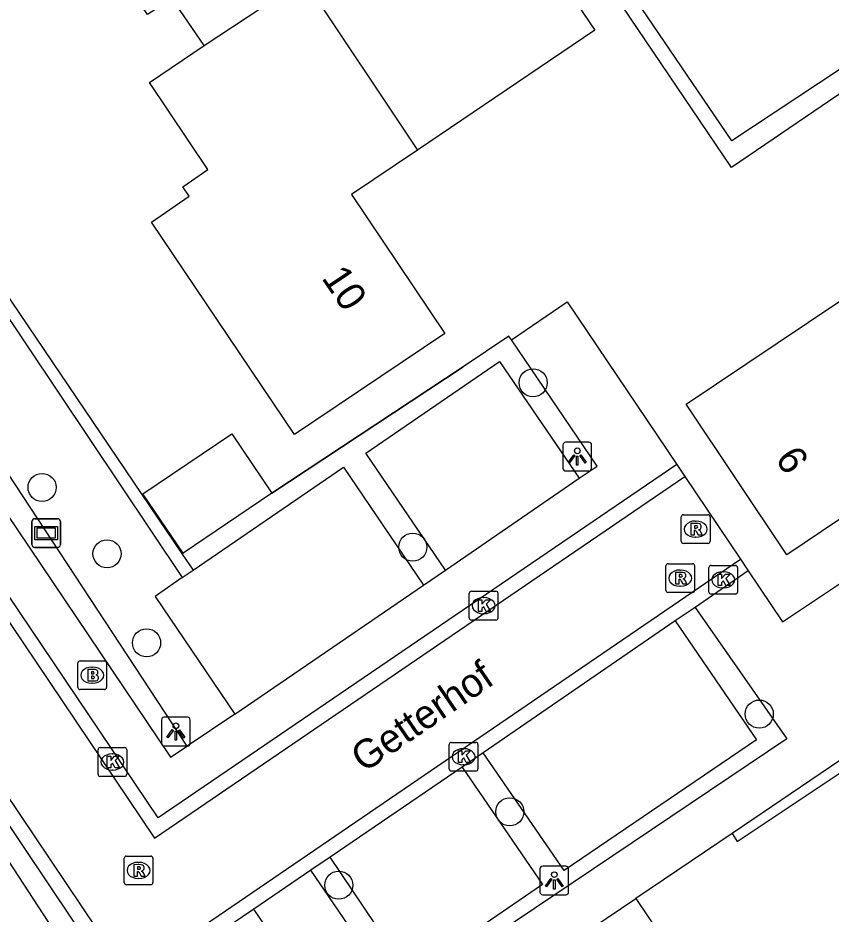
# Model space of a CAD drawing. Extents: x 158797 to 159887, y 384318 to 385255.
# Drawn here: x 158945.21 to 158973.51, y 384624.29 to 384655.5 of the extents above; entities that cross this region are included whole.
import ezdxf

# ---------------------------------------------------------------- set-up
doc = ezdxf.new("R2010")
doc.units = 0
for name, color, linetype in [('IMGEO_Boom', 7, 'Continuous'), ('IMGEO_Brandkraan', 7, 'Continuous'), ('IMGEO_Haag', 7, 'Continuous'), ('IMGEO_Hek', 7, 'Continuous'), ('IMGEO_Kolk', 7, 'Continuous'), ('IMGEO_Lichtpunt', 7, 'Continuous'), ('IMGEO_Openbare_ruimte_label', 7, 'Continuous'), ('IMGEO_Pand', 7, 'Continuous'), ('IMGEO_Pand_nummerreeks', 7, 'Continuous'), ('IMGEO_Parkeervlak_open', 7, 'Continuous'), ('IMGEO_Rijbaan_lokaal_open', 7, 'Continuous'), ('IMGEO_Rioolput', 7, 'Continuous'), ('IMGEO_Straatnaambord', 7, 'Continuous'), ('IMGEO_Voetpad_open', 7, 'Continuous')]:
    doc.layers.add(name, color=color, linetype=linetype)

msp = doc.modelspace()

# ---------------------------------------------------------------- linework, layer by layer
at = {"layer": 'IMGEO_Boom'}
for centre in [(158963.138, 384642.792), (158946.048, 384639.147), (158958.95, 384637.068), (158948.309, 384636.838), (158949.686, 384633.736), (158971.007, 384631.255), (158962.325, 384627.853), (158956.375, 384625.295)]:
    msp.add_circle(centre, 0.489, dxfattribs=at)
at = {"layer": 'IMGEO_Brandkraan'}
for p, q in [((158947.294, 384632.182), (158947.294, 384633.034)), ((158947.369, 384633.108), (158948.221, 384633.108)), ((158947.782, 384632.888), (158947.807, 384632.888)), ((158948.295, 384633.034), (158948.295, 384632.182)), ((158947.805, 384632.328), (158947.78, 384632.328)), ((158948.221, 384632.108), (158947.369, 384632.108))]:
    msp.add_line(p, q, dxfattribs=at)
for points in [[(158947.294, 384632.182), (158947.294, 384633.034)], [(158947.369, 384633.108), (158948.221, 384633.108)], [(158948.295, 384633.034), (158948.295, 384632.182)], [(158947.642, 384632.808), (158947.642, 384632.408), (158947.855, 384632.408)], [(158947.873, 384632.808), (158947.642, 384632.808)], [(158947.821, 384632.727), (158947.767, 384632.727), (158947.767, 384632.651)], [(158947.767, 384632.651), (158947.82, 384632.651)], [(158947.829, 384632.575), (158947.767, 384632.575), (158947.767, 384632.494)], [(158947.767, 384632.494), (158947.829, 384632.494)], [(158948.221, 384632.108), (158947.369, 384632.108)]]:
    msp.add_lwpolyline(points, dxfattribs=at)
for centre, radius, start, end in [((158947.371, 384633.032), 0.0765, 91.552, 178.448), ((158947.371, 384633.032), 0.0765, 91.552, 178.448), ((158948.219, 384633.032), 0.0765, 1.552, 88.448), ((158948.219, 384633.032), 0.0765, 1.552, 88.448), ((158947.822, 384632.689), 0.0379, 267.8285, 90.9355), ((158947.83, 384632.534), 0.0404, 269.8759, 90.5077), ((158947.877, 384632.663), 0.145, 59.4692, 91.5367), ((158947.902, 384632.71), 0.0922, 285.5137, 58.1501), ((158947.907, 384632.518), 0.105, 301.3115, 78.989), ((158947.861, 384632.659), 0.251, 268.6676, 293.5347), ((158947.371, 384632.184), 0.0765, 181.552, 268.448), ((158947.371, 384632.184), 0.0765, 181.552, 268.448), ((158948.219, 384632.184), 0.0765, 271.552, 358.448), ((158948.219, 384632.184), 0.0765, 271.552, 358.448)]:
    msp.add_arc(centre, radius, start, end, dxfattribs=at)
for centre, major_axis, ratio, start_param, end_param in [((158947.781, 384632.608), (-0.387, 0.002), 0.722429, 4.712389, 7.853982), ((158947.806, 384632.608), (-0.39, 0.002), 0.717154, 1.570796, 4.712389)]:
    msp.add_ellipse(centre, major_axis=major_axis, ratio=ratio, start_param=start_param, end_param=end_param, dxfattribs=at)
at = {"layer": 'IMGEO_Haag'}
for points in [[(158977.555, 384656.193), (158970.058, 384651.22), (158941.507, 384693.215), (158927, 384683.401), (158930.702, 384677.442), (158928.077, 384675.641), (158928.67, 384674.688)], [(158982.198, 384627.503), (158986.877, 384630.783), (158991.18, 384624.297), (159005.347, 384633.805), (158997.226, 384645.658), (158986.56, 384661.35), (158977.807, 384655.577), (158970.042, 384650.292), (158941.462, 384692.581), (158927.478, 384683.208), (158931.293, 384677.308), (158928.892, 384675.59), (158929.234, 384675.051), (158928.67, 384674.688)], [(158939.017, 384653.792), (158950.928, 384636.006)], [(158939.596, 384653.583), (158950.919, 384636.829)], [(158951.101, 384630.138), (158937.049, 384651.521), (158936.203, 384651.016)], [(158962.382, 384644.283), (158962.287, 384644.421), (158960.703, 384643.352), (158954.049, 384638.948)], [(158950.958, 384636.856), (158950.919, 384636.829)], [(158950.919, 384636.829), (158951.302, 384636.262)], [(158970.06, 384627.101), (158970.236, 384626.815), (158974.037, 384629.343), (158984.059, 384614.468), (158973.538, 384607.365), (158972.963, 384608.263)], [(158942.998, 384628.997), (158948.959, 384619.868)]]:
    msp.add_lwpolyline(points, dxfattribs=at)
at = {"layer": 'IMGEO_Hek'}
msp.add_lwpolyline([(158954.049, 384638.948), (158960.703, 384643.352)], dxfattribs=at)
at = {"layer": 'IMGEO_Kolk'}
for p, q in [((158969.253, 384635.506), (158969.253, 384636.358)), ((158969.328, 384636.432), (158970.18, 384636.432)), ((158970.254, 384636.358), (158970.254, 384635.506)), ((158969.741, 384636.212), (158969.766, 384636.212)), ((158960.914, 384634.604), (158960.914, 384635.456)), ((158960.989, 384635.53), (158961.841, 384635.53)), ((158961.915, 384635.456), (158961.915, 384634.604)), ((158970.18, 384635.432), (158969.328, 384635.432)), ((158969.764, 384635.652), (158969.739, 384635.652)), ((158961.402, 384635.31), (158961.427, 384635.31)), ((158961.425, 384634.75), (158961.4, 384634.75)), ((158961.841, 384634.53), (158960.989, 384634.53)), ((158948.07, 384630.086), (158948.922, 384630.086)), ((158960.217, 384629.344), (158960.217, 384630.196)), ((158960.292, 384630.27), (158961.144, 384630.27)), ((158961.218, 384630.196), (158961.218, 384629.344)), ((158947.995, 384629.16), (158947.995, 384630.012)), ((158948.483, 384629.866), (158948.508, 384629.866)), ((158948.996, 384630.012), (158948.996, 384629.16)), ((158960.705, 384630.05), (158960.73, 384630.05)), ((158960.728, 384629.49), (158960.703, 384629.49)), ((158948.506, 384629.306), (158948.481, 384629.306)), ((158961.144, 384629.27), (158960.292, 384629.27)), ((158948.922, 384629.086), (158948.07, 384629.086))]:
    msp.add_line(p, q, dxfattribs=at)
for points in [[(158969.253, 384635.506), (158969.253, 384636.358)], [(158969.328, 384636.432), (158970.18, 384636.432)], [(158970.254, 384636.358), (158970.254, 384635.506)], [(158969.574, 384636.132), (158969.697, 384636.132), (158969.697, 384635.981), (158969.827, 384636.132), (158969.991, 384636.132), (158969.845, 384635.981), (158969.998, 384635.732), (158969.846, 384635.732), (158969.761, 384635.896), (158969.697, 384635.829), (158969.697, 384635.732), (158969.574, 384635.732), (158969.574, 384636.132)], [(158960.914, 384634.604), (158960.914, 384635.456)], [(158960.989, 384635.53), (158961.841, 384635.53)], [(158961.915, 384635.456), (158961.915, 384634.604)], [(158970.18, 384635.432), (158969.328, 384635.432)], [(158961.235, 384635.23), (158961.358, 384635.23), (158961.358, 384635.079), (158961.488, 384635.23), (158961.652, 384635.23), (158961.506, 384635.079), (158961.659, 384634.83), (158961.507, 384634.83), (158961.422, 384634.994), (158961.358, 384634.927), (158961.358, 384634.83), (158961.235, 384634.83), (158961.235, 384635.23)], [(158961.841, 384634.53), (158960.989, 384634.53)], [(158948.07, 384630.086), (158948.922, 384630.086)], [(158960.217, 384629.344), (158960.217, 384630.196)], [(158960.292, 384630.27), (158961.144, 384630.27)], [(158961.218, 384630.196), (158961.218, 384629.344)], [(158947.995, 384629.16), (158947.995, 384630.012)], [(158948.316, 384629.786), (158948.439, 384629.786), (158948.439, 384629.635), (158948.569, 384629.786), (158948.733, 384629.786), (158948.587, 384629.635), (158948.74, 384629.386), (158948.588, 384629.386), (158948.503, 384629.55), (158948.439, 384629.483), (158948.439, 384629.386), (158948.316, 384629.386), (158948.316, 384629.786)], [(158948.996, 384630.012), (158948.996, 384629.16)], [(158960.538, 384629.97), (158960.661, 384629.97), (158960.661, 384629.819), (158960.791, 384629.97), (158960.955, 384629.97), (158960.809, 384629.819), (158960.962, 384629.57), (158960.81, 384629.57), (158960.725, 384629.734), (158960.661, 384629.667), (158960.661, 384629.57), (158960.538, 384629.57), (158960.538, 384629.97)], [(158961.144, 384629.27), (158960.292, 384629.27)], [(158948.922, 384629.086), (158948.07, 384629.086)]]:
    msp.add_lwpolyline(points, dxfattribs=at)
for centre, start, end in [((158969.33, 384636.356), 91.552, 178.448), ((158969.33, 384636.356), 91.552, 178.448), ((158970.178, 384636.356), 1.552, 88.448), ((158970.178, 384636.356), 1.552, 88.448), ((158960.991, 384635.454), 91.552, 178.448), ((158960.991, 384635.454), 91.552, 178.448), ((158961.839, 384635.454), 1.552, 88.448), ((158961.839, 384635.454), 1.552, 88.448), ((158969.33, 384635.508), 181.552, 268.448), ((158969.33, 384635.508), 181.552, 268.448), ((158970.178, 384635.508), 271.552, 358.448), ((158970.178, 384635.508), 271.552, 358.448), ((158960.991, 384634.606), 181.552, 268.448), ((158960.991, 384634.606), 181.552, 268.448), ((158961.839, 384634.606), 271.552, 358.448), ((158961.839, 384634.606), 271.552, 358.448), ((158948.072, 384630.01), 91.552, 178.448), ((158948.072, 384630.01), 91.552, 178.448), ((158948.92, 384630.01), 1.552, 88.448), ((158948.92, 384630.01), 1.552, 88.448), ((158960.294, 384630.194), 91.552, 178.448), ((158960.294, 384630.194), 91.552, 178.448), ((158961.142, 384630.194), 1.552, 88.448), ((158961.142, 384630.194), 1.552, 88.448), ((158948.072, 384629.162), 181.552, 268.448), ((158948.072, 384629.162), 181.552, 268.448), ((158948.92, 384629.162), 271.552, 358.448), ((158948.92, 384629.162), 271.552, 358.448), ((158960.294, 384629.346), 181.552, 268.448), ((158960.294, 384629.346), 181.552, 268.448), ((158961.142, 384629.346), 271.552, 358.448), ((158961.142, 384629.346), 271.552, 358.448)]:
    msp.add_arc(centre, 0.0765, start, end, dxfattribs=at)
for centre, major_axis, ratio, start_param, end_param in [((158969.74, 384635.932), (-0.387, 0.002), 0.722429, 4.712389, 7.853982), ((158969.765, 384635.932), (-0.39, 0.002), 0.717154, 1.570796, 4.712389), ((158961.401, 384635.03), (-0.387, 0.002), 0.722429, 4.712389, 7.853982), ((158961.426, 384635.03), (-0.39, 0.002), 0.717154, 1.570796, 4.712389), ((158948.482, 384629.586), (-0.387, 0.002), 0.722429, 4.712389, 7.853982), ((158948.507, 384629.586), (-0.39, 0.002), 0.717154, 1.570796, 4.712389), ((158960.704, 384629.77), (-0.387, 0.002), 0.722429, 4.712389, 7.853982), ((158960.729, 384629.77), (-0.39, 0.002), 0.717154, 1.570796, 4.712389)]:
    msp.add_ellipse(centre, major_axis=major_axis, ratio=ratio, start_param=start_param, end_param=end_param, dxfattribs=at)
at = {"layer": 'IMGEO_Lichtpunt'}
for p, q in [((158965.078, 384640.72), (158964.27, 384640.72)), ((158965.078, 384640.72), (158964.27, 384640.72)), ((158964.176, 384640.625), (158964.176, 384639.818)), ((158964.176, 384640.625), (158964.176, 384639.818)), ((158965.172, 384639.818), (158965.172, 384640.625)), ((158965.172, 384639.818), (158965.172, 384640.625)), ((158964.27, 384639.724), (158965.078, 384639.724)), ((158964.27, 384639.724), (158965.078, 384639.724)), ((158950.206, 384631.048), (158950.206, 384630.241)), ((158950.206, 384631.048), (158950.206, 384630.241)), ((158951.108, 384631.143), (158950.3, 384631.143)), ((158951.108, 384631.143), (158950.3, 384631.143)), ((158951.202, 384630.241), (158951.202, 384631.048)), ((158951.202, 384630.241), (158951.202, 384631.048)), ((158950.3, 384630.147), (158951.108, 384630.147)), ((158950.3, 384630.147), (158951.108, 384630.147)), ((158963.376, 384625.865), (158963.376, 384625.058)), ((158963.376, 384625.865), (158963.376, 384625.058)), ((158964.278, 384625.96), (158963.47, 384625.96)), ((158964.278, 384625.96), (158963.47, 384625.96)), ((158964.372, 384625.058), (158964.372, 384625.865)), ((158964.372, 384625.058), (158964.372, 384625.865)), ((158963.47, 384624.964), (158964.278, 384624.964)), ((158963.47, 384624.964), (158964.278, 384624.964))]:
    msp.add_line(p, q, dxfattribs=at)
for points in [[(158964.55, 384640.289), (158964.589, 384640.261), (158964.401, 384639.999), (158964.363, 384640.026), (158964.55, 384640.289)], [(158964.652, 384640.241), (158964.699, 384640.241), (158964.699, 384639.919), (158964.652, 384639.919), (158964.652, 384640.241)], [(158964.762, 384640.261), (158964.8, 384640.288), (158964.987, 384640.026), (158964.948, 384639.998), (158964.762, 384640.261)], [(158950.58, 384630.712), (158950.619, 384630.684), (158950.431, 384630.422), (158950.393, 384630.449), (158950.58, 384630.712)], [(158950.792, 384630.684), (158950.83, 384630.711), (158951.017, 384630.449), (158950.978, 384630.421), (158950.792, 384630.684)], [(158950.682, 384630.664), (158950.729, 384630.664), (158950.729, 384630.342), (158950.682, 384630.342), (158950.682, 384630.664)], [(158963.75, 384625.529), (158963.789, 384625.501), (158963.601, 384625.239), (158963.563, 384625.266), (158963.75, 384625.529)], [(158963.852, 384625.481), (158963.899, 384625.481), (158963.899, 384625.159), (158963.852, 384625.159), (158963.852, 384625.481)], [(158963.962, 384625.501), (158964, 384625.528), (158964.187, 384625.266), (158964.148, 384625.238), (158963.962, 384625.501)]]:
    msp.add_lwpolyline(points, dxfattribs=at)
for centre in [(158964.675, 384640.423), (158950.705, 384630.846), (158963.875, 384625.663)]:
    msp.add_circle(centre, 0.0994, dxfattribs=at)
for centre, start, end in [((158964.27, 384640.625), 90, 180), ((158964.27, 384640.625), 90, 180), ((158965.078, 384640.625), 0, 90), ((158965.078, 384640.625), 0, 90), ((158964.27, 384639.818), 180, 270), ((158964.27, 384639.818), 180, 270), ((158965.078, 384639.818), 270, 0), ((158965.078, 384639.818), 270, 360), ((158950.3, 384631.048), 90, 180), ((158950.3, 384631.048), 90, 180), ((158951.108, 384631.048), 0, 90), ((158951.108, 384631.048), 0, 90), ((158950.3, 384630.241), 180, 270), ((158950.3, 384630.241), 180, 270), ((158951.108, 384630.241), 270, 0), ((158951.108, 384630.241), 270, 360), ((158963.47, 384625.865), 90, 180), ((158963.47, 384625.865), 90, 180), ((158964.278, 384625.865), 0, 90), ((158964.278, 384625.865), 0, 90), ((158963.47, 384625.058), 180, 270), ((158963.47, 384625.058), 180, 270), ((158964.278, 384625.058), 270, 0), ((158964.278, 384625.058), 270, 360)]:
    msp.add_arc(centre, 0.0946, start, end, dxfattribs=at)
at = {"layer": 'IMGEO_Pand'}
for points in [[(158951.688, 384654.533), (158950.579, 384656.17), (158949.72, 384655.614), (158947.442, 384658.977), (158948.29, 384659.551), (158947.666, 384660.472), (158949.703, 384661.834), (158948.108, 384664.221), (158953.136, 384667.637), (158959.371, 384658.409), (158961.876, 384660.105), (158965.286, 384655.074), (158959.111, 384650.898)], [(158951.688, 384654.533), (158955.154, 384656.841), (158959.111, 384650.898)], [(158959.111, 384650.898), (158956.816, 384649.346), (158960.067, 384644.506), (158954.829, 384640.992), (158949.853, 384648.386), (158951.172, 384649.295), (158950.952, 384649.62), (158951.817, 384650.223), (158949.791, 384653.25), (158951.688, 384654.533)], [(158978.456, 384637.583), (158976.795, 384640.054), (158971.967, 384636.804), (158968.458, 384642.042), (158975.882, 384647.025), (158976.77, 384645.705), (158977.111, 384645.927), (158977.701, 384645.062), (158980.723, 384647.095), (158982.012, 384645.186)], [(158950.958, 384636.856), (158949.554, 384638.926), (158952.648, 384641.018), (158954.049, 384638.948)], [(158954.049, 384638.948), (158950.958, 384636.856)], [(158963.155, 384622.43), (158966.711, 384624.833)], [(158966.711, 384624.833), (158968.976, 384621.467), (158972.244, 384623.666), (158976.039, 384618.066), (158979.246, 384620.233), (158981.95, 384616.231), (158976.507, 384612.552), (158975.269, 384614.383), (158970.878, 384611.416)]]:
    msp.add_lwpolyline(points, dxfattribs=at)
at = {"layer": 'IMGEO_Parkeervlak_open'}
for points in [[(158960.089, 384636.266), (158957.311, 384640.347), (158961.963, 384643.532), (158964.741, 384639.472)], [(158951.302, 384636.262), (158956.541, 384639.854), (158959.328, 384635.75)], [(158950.928, 384636.006), (158949.979, 384635.355), (158952.761, 384631.247)], [(158950.928, 384636.006), (158951.302, 384636.262)], [(158968.085, 384634.504), (158970.914, 384630.355), (158964.22, 384625.803), (158961.404, 384629.901)], [(158960.669, 384629.404), (158963.469, 384625.318), (158958.849, 384622.147), (158956.071, 384626.266)]]:
    msp.add_lwpolyline(points, dxfattribs=at)
at = {"layer": 'IMGEO_Rijbaan_lokaal_open'}
for points in [[(158968.134, 384639.947), (158950.085, 384627.638), (158924.353, 384665.905), (158921.285, 384670.455)], [(158920.881, 384670.173), (158923.955, 384665.633), (158949.957, 384626.932), (158968.418, 384639.524)], [(158968.134, 384639.947), (158968.418, 384639.524)], [(158968.418, 384639.524), (158970.35, 384636.65)], [(158918.871, 384617.212), (158941.972, 384632.67), (158949.064, 384622.099), (158970.35, 384636.65)], [(158970.35, 384636.65), (158970.621, 384636.247)], [(158970.621, 384636.247), (158968.774, 384634.969)], [(158968.774, 384634.969), (158968.085, 384634.504)], [(158968.085, 384634.504), (158961.404, 384629.901)], [(158953.415, 384624.464), (158948.9, 384621.402), (158941.838, 384631.945), (158930.65, 384624.451)], [(158961.404, 384629.901), (158960.669, 384629.404)], [(158960.669, 384629.404), (158956.071, 384626.266)], [(158956.071, 384626.266), (158955.406, 384625.815)], [(158955.406, 384625.815), (158953.415, 384624.464)]]:
    msp.add_lwpolyline(points, dxfattribs=at)
at = {"layer": 'IMGEO_Rioolput'}
for p, q in [((158968.369, 384638.197), (158969.221, 384638.197)), ((158968.294, 384637.271), (158968.294, 384638.123)), ((158968.782, 384637.977), (158968.807, 384637.977)), ((158969.295, 384638.123), (158969.295, 384637.271)), ((158968.805, 384637.417), (158968.78, 384637.417)), ((158969.221, 384637.197), (158968.369, 384637.197)), ((158967.758, 384635.565), (158967.758, 384636.417)), ((158967.833, 384636.491), (158968.685, 384636.491)), ((158968.759, 384636.417), (158968.759, 384635.565)), ((158968.246, 384636.271), (158968.271, 384636.271)), ((158968.269, 384635.711), (158968.244, 384635.711)), ((158968.685, 384635.491), (158967.833, 384635.491)), ((158948.906, 384625.385), (158948.906, 384626.237)), ((158948.981, 384626.311), (158949.833, 384626.311)), ((158949.394, 384626.091), (158949.419, 384626.091)), ((158949.907, 384626.237), (158949.907, 384625.385)), ((158949.417, 384625.531), (158949.392, 384625.531)), ((158949.833, 384625.311), (158948.981, 384625.311))]:
    msp.add_line(p, q, dxfattribs=at)
for points in [[(158968.369, 384638.197), (158969.221, 384638.197)], [(158968.294, 384637.271), (158968.294, 384638.123)], [(158968.883, 384637.895), (158968.631, 384637.897), (158968.631, 384637.497)], [(158969.295, 384638.123), (158969.295, 384637.271)], [(158968.631, 384637.497), (158968.755, 384637.497), (158968.755, 384637.659), (158968.766, 384637.659)], [(158968.809, 384637.816), (158968.755, 384637.816), (158968.755, 384637.735)], [(158968.755, 384637.735), (158968.807, 384637.735)], [(158968.813, 384637.63), (158968.884, 384637.497), (158969.024, 384637.497), (158968.959, 384637.623)], [(158969.221, 384637.197), (158968.369, 384637.197)], [(158967.758, 384635.565), (158967.758, 384636.417)], [(158967.833, 384636.491), (158968.685, 384636.491)], [(158968.759, 384636.417), (158968.759, 384635.565)], [(158968.347, 384636.189), (158968.095, 384636.191), (158968.095, 384635.791)], [(158968.273, 384636.11), (158968.219, 384636.11), (158968.219, 384636.029)], [(158968.219, 384636.029), (158968.271, 384636.029)], [(158968.095, 384635.791), (158968.219, 384635.791), (158968.219, 384635.953), (158968.23, 384635.953)], [(158968.277, 384635.924), (158968.348, 384635.791), (158968.488, 384635.791), (158968.423, 384635.917)], [(158968.685, 384635.491), (158967.833, 384635.491)], [(158948.906, 384625.385), (158948.906, 384626.237)], [(158948.981, 384626.311), (158949.833, 384626.311)], [(158949.495, 384626.009), (158949.243, 384626.011), (158949.243, 384625.611)], [(158949.907, 384626.237), (158949.907, 384625.385)], [(158949.243, 384625.611), (158949.367, 384625.611), (158949.367, 384625.773), (158949.378, 384625.773)], [(158949.421, 384625.93), (158949.367, 384625.93), (158949.367, 384625.849)], [(158949.367, 384625.849), (158949.419, 384625.849)], [(158949.425, 384625.744), (158949.496, 384625.611), (158949.636, 384625.611), (158949.571, 384625.737)], [(158949.833, 384625.311), (158948.981, 384625.311)]]:
    msp.add_lwpolyline(points, dxfattribs=at)
for centre, radius, start, end in [((158968.371, 384638.121), 0.0765, 91.552, 178.448), ((158968.371, 384638.121), 0.0765, 91.552, 178.448), ((158969.219, 384638.121), 0.0765, 1.552, 88.448), ((158969.219, 384638.121), 0.0765, 1.552, 88.448), ((158968.882, 384637.785), 0.109, 350.3612, 89.416), ((158968.765, 384637.606), 0.0533, 26.0293, 88.6989), ((158968.791, 384637.924), 0.19, 274.7715, 282.9687), ((158968.815, 384637.72), 0.0964, 77.0061, 93.1865), ((158968.829, 384637.777), 0.0378, 276.6634, 79.6772), ((158968.88, 384637.785), 0.112, 277.5842, 350.9817), ((158968.864, 384637.57), 0.108, 29.5134, 73.7905), ((158968.371, 384637.273), 0.0765, 181.552, 268.448), ((158968.371, 384637.273), 0.0765, 181.552, 268.448), ((158969.219, 384637.273), 0.0765, 271.552, 358.448), ((158969.219, 384637.273), 0.0765, 271.552, 358.448), ((158967.835, 384636.415), 0.0765, 91.552, 178.448), ((158967.835, 384636.415), 0.0765, 91.552, 178.448), ((158968.683, 384636.415), 0.0765, 1.552, 88.448), ((158968.683, 384636.415), 0.0765, 1.552, 88.448), ((158968.255, 384636.218), 0.19, 274.7715, 282.9687), ((158968.279, 384636.014), 0.0964, 77.0061, 93.1865), ((158968.293, 384636.071), 0.0378, 276.6634, 79.6772), ((158968.346, 384636.079), 0.109, 350.3612, 89.416), ((158968.344, 384636.079), 0.112, 277.5842, 350.9817), ((158968.229, 384635.9), 0.0533, 26.0293, 88.6989), ((158968.328, 384635.864), 0.108, 29.5134, 73.7905), ((158967.835, 384635.567), 0.0765, 181.552, 268.448), ((158967.835, 384635.567), 0.0765, 181.552, 268.448), ((158968.683, 384635.567), 0.0765, 271.552, 358.448), ((158968.683, 384635.567), 0.0765, 271.552, 358.448), ((158948.983, 384626.235), 0.0765, 91.552, 178.448), ((158948.983, 384626.235), 0.0765, 91.552, 178.448), ((158949.494, 384625.899), 0.109, 350.3612, 89.416), ((158949.831, 384626.235), 0.0765, 1.552, 88.448), ((158949.831, 384626.235), 0.0765, 1.552, 88.448), ((158949.377, 384625.72), 0.0533, 26.0293, 88.6989), ((158949.403, 384626.038), 0.19, 274.7715, 282.9687), ((158949.427, 384625.834), 0.0964, 77.0061, 93.1865), ((158949.441, 384625.891), 0.0378, 276.6634, 79.6772), ((158949.492, 384625.899), 0.112, 277.5842, 350.9817), ((158949.476, 384625.684), 0.108, 29.5134, 73.7905), ((158948.983, 384625.387), 0.0765, 181.552, 268.448), ((158948.983, 384625.387), 0.0765, 181.552, 268.448), ((158949.831, 384625.387), 0.0765, 271.552, 358.448), ((158949.831, 384625.387), 0.0765, 271.552, 358.448)]:
    msp.add_arc(centre, radius, start, end, dxfattribs=at)
for centre, major_axis, ratio, start_param, end_param in [((158968.781, 384637.697), (-0.387, 0.002), 0.722429, 4.712389, 7.853982), ((158968.806, 384637.697), (-0.39, 0.002), 0.717154, 1.570796, 4.712389), ((158968.245, 384635.991), (-0.387, 0.002), 0.722429, 4.712389, 7.853982), ((158968.27, 384635.991), (-0.39, 0.002), 0.717154, 1.570796, 4.712389), ((158949.393, 384625.811), (-0.387, 0.002), 0.722429, 4.712389, 7.853982), ((158949.418, 384625.811), (-0.39, 0.002), 0.717154, 1.570796, 4.712389)]:
    msp.add_ellipse(centre, major_axis=major_axis, ratio=ratio, start_param=start_param, end_param=end_param, dxfattribs=at)
at = {"layer": 'IMGEO_Straatnaambord'}
for p, q in [((158945.697, 384637.157), (158945.697, 384637.957)), ((158945.697, 384637.957), (158945.697, 384637.157)), ((158945.797, 384638.057), (158946.587, 384638.057)), ((158946.587, 384638.057), (158945.797, 384638.057)), ((158946.687, 384637.957), (158946.687, 384637.157)), ((158946.687, 384637.157), (158946.687, 384637.957)), ((158946.587, 384637.057), (158945.797, 384637.057)), ((158945.797, 384637.057), (158946.587, 384637.057))]:
    msp.add_line(p, q, dxfattribs=at)
for points in [[(158945.798, 384637.789), (158946.586, 384637.789), (158946.586, 384637.325), (158945.798, 384637.325), (158945.798, 384637.789)], [(158945.863, 384637.724), (158945.863, 384637.39), (158946.521, 384637.39), (158946.521, 384637.724), (158945.863, 384637.724)]]:
    msp.add_lwpolyline(points, dxfattribs=at)
for centre, start, end in [((158945.797, 384637.957), 90, 180), ((158945.797, 384637.957), 90, 180), ((158946.587, 384637.957), 0, 90), ((158946.587, 384637.957), 360, 90), ((158945.797, 384637.157), 180, 270), ((158945.797, 384637.157), 180, 270), ((158946.587, 384637.157), 270, 0), ((158946.587, 384637.157), 270, 0)]:
    msp.add_arc(centre, 0.1, start, end, dxfattribs=at)
at = {"layer": 'IMGEO_Voetpad_open'}
for points in [[(158936.203, 384651.016), (158950.52, 384629.75), (158951.101, 384630.138)], [(158962.382, 384644.283), (158964.327, 384645.61), (158968.134, 384639.947)], [(158964.741, 384639.472), (158965.367, 384639.89), (158962.382, 384644.283)], [(158960.089, 384636.266), (158964.741, 384639.472)], [(158970.621, 384636.247), (158971.818, 384634.466), (158975.716, 384637.065), (158980.972, 384629.328), (158982.198, 384627.503)], [(158959.328, 384635.75), (158960.089, 384636.266)], [(158952.761, 384631.247), (158959.328, 384635.75)], [(158968.774, 384634.969), (158971.961, 384630.395), (158958.47, 384621.32), (158955.406, 384625.815)], [(158952.761, 384631.247), (158951.101, 384630.138)], [(158974.168, 384629.884), (158970.06, 384627.101)], [(158970.06, 384627.101), (158966.711, 384624.833)], [(158954.158, 384623.366), (158953.415, 384624.464)]]:
    msp.add_lwpolyline(points, dxfattribs=at)

# ---------------------------------------------------------------- texts
at = {"layer": 'IMGEO_Openbare_ruimte_label'}
msp.add_text('Getterhof', height=1, rotation=34.3256, dxfattribs=at).set_placement((158957.246, 384629.194))
at = {"layer": 'IMGEO_Pand_nummerreeks'}
for s, rotation, p in [('10', 303.8832, (158955.754, 384646.444)), ('6', 303.8193, (158971.535, 384640.143))]:
    msp.add_text(s, height=1, rotation=rotation, dxfattribs=at).set_placement(p)

doc.saveas('drawing.dxf')
